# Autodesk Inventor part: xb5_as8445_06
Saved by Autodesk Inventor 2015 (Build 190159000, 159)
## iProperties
Created: 2018-04
Part Number: xb5_as8445_06
Checked By: TraceParts S.A.
Material: Generic
Catalog Web Link: www.traceparts.com
Document SubType Name: Modeling
Designer: TraceParts
Density: 1 g/cm^3
Appearance: Default
Company: TraceParts S.A.
Author: TraceParts
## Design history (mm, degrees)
feature "xb5_as8445_06.ipt"
body "Solid1"
